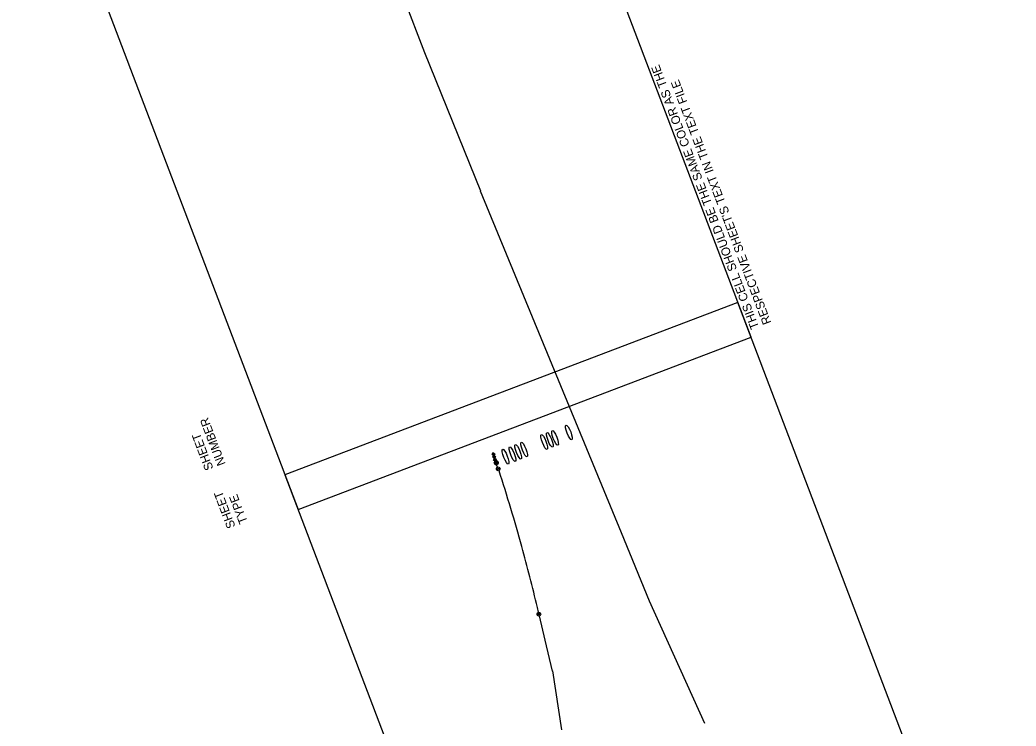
# Model space of a CAD drawing. Extents: x 601462 to 605493, y 331960 to 402715.
# Drawn here: x 602409 to 604414, y 350656 to 352077 of the extents above; entities that cross this region are included whole.
import ezdxf

# ---------------------------------------------------------------- set-up
doc = ezdxf.new("R2010")
doc.units = 0
for name, color, linetype in [('P_FTMS', 7, 'Continuous'), ('P_FTMSConduit', 7, 'Continuous'), ('P_MISC_TXT_2A (Construction)', 7, 'Continuous'), ('P_MISC_TXT_2B (Construction)', 7, 'Continuous')]:
    doc.layers.add(name, color=color, linetype=linetype)

# ---------------------------------------------------------------- blocks, each defined once
blk = doc.blocks.new('FMD')
at = {"layer": 'P_FTMS'}
for p, q in [((17, 18), (-17, 18)), ((-16, 16), (-16, 18)), ((16, 16), (-16, 16)), ((-15, 15), (-15, 20)), ((15, 19), (-15, 19)), ((15, 15), (-15, 15)), ((14, 20), (-14, 20)), ((13, 22), (-13, 22)), ((-13, 13), (-13, 21)), ((13, 13), (-13, 13)), ((-12, 12), (-12, 23)), ((12, 12), (-12, 12)), ((11, 23), (-11, 23)), ((10, 25), (-10, 25)), ((-10, 10), (-10, 24)), ((10, 10), (-10, 10)), ((-9, 9), (-9, 26)), ((9, 9), (-9, 9)), ((8, 26), (-8, 26)), ((7, 28), (-7, 28)), ((-7, 7), (-7, 27)), ((7, 7), (-7, 7)), ((-6, 6), (-6, 29)), ((6, 6), (-6, 6)), ((5, 29), (-5, 29)), ((4, 31), (-4, 31)), ((-4, 4), (-4, 30)), ((4, 4), (-4, 4)), ((-3, 3), (-3, 32)), ((3, 3), (-3, 3)), ((2, 32), (-2, 32)), ((1, 34), (-1, 34)), ((-1, 1), (-1, 33)), ((1, 1), (-1, 1)), ((0, 0), (0, 34)), ((1, 1), (1, 33)), ((3, 3), (3, 32)), ((4, 4), (4, 30)), ((6, 6), (6, 29)), ((7, 7), (7, 27)), ((9, 9), (9, 26)), ((10, 10), (10, 24)), ((12, 12), (12, 23)), ((13, 13), (13, 21)), ((15, 15), (15, 20)), ((16, 16), (16, 18))]:
    blk.add_line(p, q, dxfattribs=at)
blk.add_lwpolyline([(-17, 17), (0, 34), (17, 17), (0, 0)], close=True, dxfattribs=at)
blk = doc.blocks.new('_U230')
at = {"layer": 'P_FTMS'}
for p, q in [((12.1, 1.6), (-12.2, -0.1)), ((11.8, 3), (-12.1, 1.4)), ((11.9, 2.3), (-12.1, 0.6)), ((12.1, 0.8), (-12.1, -0.8)), ((12.1, 0.1), (-12.1, -1.6)), ((11.6, 3.7), (-12, 2.1)), ((-11.9, 2.5), (-11.4, -4.2)), ((11.3, 4.4), (-11.8, 2.9)), ((11, 5.2), (-11.6, 3.6)), ((10.6, 5.9), (-11.4, 4.4)), ((-11.3, 4.5), (-10.6, -6)), ((10.2, 6.6), (-11, 5.1)), ((9.8, 7.3), (-10.7, 5.9)), ((-10.7, 5.9), (-9.8, -7.2)), ((9.2, 8), (-10.2, 6.6)), ((-10, 6.9), (-9, -8.2)), ((8.6, 8.6), (-9.7, 7.4)), ((-9.3, 7.8), (-8.2, -9)), ((7.8, 9.3), (-9, 8.2)), ((-8.6, 8.5), (-7.4, -9.6)), ((6.9, 10), (-8.2, 9)), ((-8, 9.2), (-6.6, -10.2)), ((-7.3, 9.7), (-5.9, -10.6)), ((5.8, 10.7), (-7.2, 9.8)), ((-6.6, 10.3), (-5.1, -11)), ((4.5, 11.3), (-6, 10.6)), ((-5.9, 10.7), (-4.4, -11.4)), ((-5.1, 11), (-3.6, -11.6)), ((-4.4, 11.3), (-2.9, -11.8)), ((2.5, 11.9), (-4.1, 11.5)), ((-3.7, 11.6), (-2.1, -12)), ((-3, 11.8), (-1.4, -12.1)), ((-2.3, 12), (-0.6, -12.2)), ((-1.6, 12.1), (0.1, -12.2)), ((-0.8, 12.1), (0.8, -12.1)), ((-0.1, 12.2), (1.6, -12.1)), ((0.6, 12.1), (2.3, -11.9)), ((1.4, 12.1), (3, -11.8)), ((2.1, 12), (3.7, -11.6)), ((2.9, 11.8), (4.4, -11.3)), ((3.6, 11.6), (5.1, -11)), ((4.4, 11.3), (5.9, -10.7)), ((5.1, 11), (6.6, -10.2)), ((5.9, 10.6), (7.3, -9.8)), ((6.6, 10.2), (8, -9.2)), ((7.4, 9.7), (8.6, -8.6)), ((8.2, 9), (9.3, -7.8)), ((9, 8.2), (10, -6.9)), ((9.8, 7.2), (10.7, -5.8)), ((10.6, 5.9), (11.3, -4.5)), ((11.5, 4), (11.9, -2.5)), ((12.1, -0.6), (-12, -2.3)), ((12.1, -1.4), (-11.8, -3)), ((12, -2.1), (-11.6, -3.7)), ((11.8, -2.9), (-11.3, -4.4)), ((11.6, -3.6), (-11, -5.1)), ((11.3, -4.4), (-10.7, -5.9)), ((11.1, -5.1), (-10.2, -6.6)), ((10.6, -5.9), (-9.8, -7.3)), ((10.2, -6.6), (-9.2, -8)), ((9.6, -7.4), (-8.5, -8.6)), ((9, -8.2), (-7.8, -9.3)), ((8.2, -9), (-6.9, -10)), ((7.3, -9.8), (-5.8, -10.7)), ((6, -10.6), (-4.5, -11.3)), ((4.1, -11.5), (-2.6, -11.9))]:
    blk.add_line(p, q, dxfattribs=at)
blk.add_circle((0, 0), 12.2, dxfattribs=at)

msp = doc.modelspace()

# ---------------------------------------------------------------- linework, layer by layer
at = {"layer": 'P_FTMS'}
for centre in [(603372, 351173.7), (603453.9, 350881)]:
    msp.add_circle(centre, 3.75, dxfattribs=at)
for centre, start, end in [((603371.6, 351178.2), 222.4831, 328.7387), ((603372.5, 351169.3), 42.4831, 148.7387), ((603453.4, 350885.5), 222.4831, 328.7387), ((603454.3, 350876.5), 42.4831, 148.7387)]:
    msp.add_arc(centre, 3.75, start, end, dxfattribs=at)
for centre in [(603514.3, 351246.7), (603464.5, 351227.7), (603475.8, 351232), (603486.3, 351236.1), (603412.2, 351207.7), (603424.2, 351212.4), (603386.8, 351198), (603400.6, 351203.3)]:
    msp.add_ellipse(centre, major_axis=(-5.8, 14.9), ratio=0.23471, dxfattribs=at)
at = {"layer": 'P_FTMSConduit'}
for p, q in [((603165.2, 352164.9), (603223.8, 352011.2)), ((603223.7, 352011.3), (603336, 351733.1)), ((603335.9, 351733.2), (603619.4, 351045.5)), ((603368, 351181.8), (603370.8, 351177.3)), ((603619.4, 351045.5), (603676.1, 350908)), ((603676.1, 350908.1), (603787.3, 350661.9)), ((603453, 350885.4), (603450.8, 350894.8)), ((603466.4, 350828.6), (603454.8, 350877.7)), ((603481, 350766.6), (603466.4, 350828.6)), ((603480.9, 350766.9), (603499.6, 350648.5))]:
    msp.add_line(p, q, dxfattribs=at)
for start, end in [(15.3877, 18.0896), (13.2512, 15.3877)]:
    msp.add_arc((600155.9, 350118.9), 3385, start, end, dxfattribs=at)
at = {"layer": 'P_MISC_TXT_2A (Construction)'}
msp.add_lwpolyline([(604414.2, 350036.4), (603854.1, 351508.5), (602942.8, 351161.8), (603502.9, 349689.7)], close=True, dxfattribs=at)
at = {"layer": 'P_MISC_TXT_2B (Construction)'}
msp.add_lwpolyline([(603880.8, 351438.4), (603320.7, 352910.4), (602409.4, 352563.7), (602969.5, 351091.7)], close=True, dxfattribs=at)

# ---------------------------------------------------------------- block references
at = {"layer": 'P_FTMS'}
for name, p, xscale, yscale, rotation in [('FMD', (603359.6, 351202.6), 0.16404166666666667, 0.16404166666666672, -74.13394312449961), ('FMD', (603361.3, 351196.8), 0.16404166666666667, 0.16404166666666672, -74.13394312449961), ('FMD', (603362.8, 351191.4), 0.16404166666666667, 0.16404166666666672, -74.13394312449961), ('_U230', (603367.9, 351185.8), 0.32808333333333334, 0.32808333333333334, 19.97319264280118)]:
    msp.add_blockref(name, p, dxfattribs=dict(at, xscale=xscale, yscale=yscale, rotation=rotation))

# ---------------------------------------------------------------- texts
at = {"layer": 'P_MISC_TXT_2B (Construction)'}
for s, p in [('THIS CELL SHOULD BE THE SAME COLOR AS THE', (603897.3, 351458.5)), ("RESPECTIVE SHEET'S TEXT IN THE TEXT FILE", (603921.8, 351467.9)), ('NUMBER', (602823.6, 351183.7)), ('SHEET', (602799.1, 351174.4)), ('SHEET', (602843.5, 351057.6)), ('TYPE', (602868, 351066.9))]:
    msp.add_text(s, height=17.5, rotation=110.8314, dxfattribs=at).set_placement(p)

doc.saveas('drawing.dxf')
